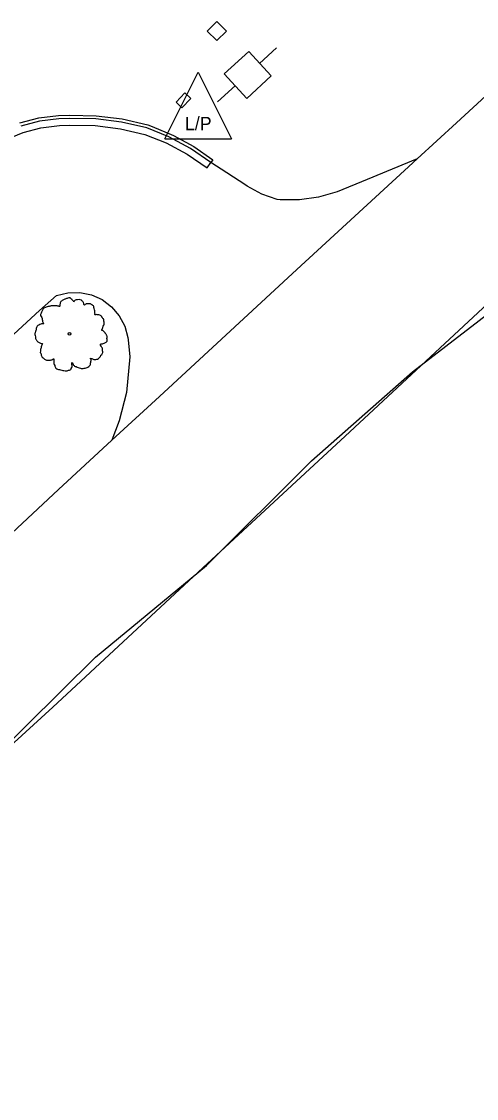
# Model space of a CAD drawing. Extents: x 2161152 to 2175754, y 602179 to 617749.
# Drawn here: x 2162836.6 to 2162905, y 605296.7 to 605458.4 of the extents above; entities that cross this region are included whole.
import ezdxf

# ---------------------------------------------------------------- set-up
doc = ezdxf.new("R2010")
doc.units = 0
for name, color, linetype in [('RD_EX_Conc_Curb', 7, 'Continuous'), ('RD_EX_Conc_Gutter', 7, 'Continuous'), ('RD_EX_Parking_Asphalt', 7, 'Continuous'), ('RD_EX_Road', 7, 'Continuous'), ('RD_EX_UT', 7, 'Continuous'), ('RD_EX_VEG', 7, 'Continuous')]:
    doc.layers.add(name, color=color, linetype=linetype)

msp = doc.modelspace()

# ---------------------------------------------------------------- linework, layer by layer
at = {"layer": 'RD_EX_Conc_Curb'}
msp.add_lwpolyline([(2162836.4, 605443.12), (2162839.27, 605443.88), (2162842.2, 605444.23), (2162843.89, 605444.31), (2162847.84, 605444.22), (2162851.76, 605443.73), (2162855.63, 605442.85), (2162856.29, 605442.61), (2162859.48, 605441.24), (2162862.52, 605439.57), (2162865.37, 605437.61), (2162865.17, 605437.32), (2162865.09, 605437.19), (2162862.04, 605439.28), (2162858.78, 605441.02), (2162855.48, 605442.37), (2162851.68, 605443.24), (2162847.8, 605443.72), (2162843.9, 605443.81), (2162842.25, 605443.73), (2162839.36, 605443.38), (2162836.56, 605442.65)], dxfattribs=at)
at = {"layer": 'RD_EX_Conc_Gutter'}
msp.add_lwpolyline([(2162834.32, 605440.64), (2162836.88, 605441.7), (2162839.55, 605442.4), (2162842.33, 605442.74), (2162843.91, 605442.81), (2162847.73, 605442.73), (2162851.5, 605442.26), (2162855.18, 605441.41), (2162858.36, 605440.12), (2162861.52, 605438.42), (2162864.53, 605436.37), (2162865.09, 605437.19)], dxfattribs=at)
at = {"layer": 'RD_EX_Parking_Asphalt'}
for points in [[(2162896.04, 605437.72), (2162888.57, 605434.62), (2162884.07, 605432.78), (2162881.27, 605431.99), (2162878.39, 605431.59), (2162875.48, 605431.58), (2162875.06, 605431.61), (2162872.72, 605432.44), (2162870.55, 605433.64), (2162870.32, 605433.79), (2162867.49, 605435.65), (2162865.09, 605437.19)], [(2162832.21, 605408.43), (2162839.36, 605414.97), (2162841.9, 605417.21), (2162843.62, 605417.64), (2162845.4, 605417.68), (2162847.14, 605417.33), (2162848.76, 605416.6), (2162850.18, 605415.54), (2162851.33, 605414.18), (2162852.15, 605412.61), (2162852.61, 605410.9), (2162852.66, 605410.57), (2162852.91, 605407.99), (2162852.41, 605402.64), (2162851.29, 605398.43), (2162850.22, 605395.49)]]:
    msp.add_lwpolyline(points, dxfattribs=at)
at = {"layer": 'RD_EX_Road'}
for points in [[(2162917.02, 605457), (2162901.98, 605443.14), (2162896.04, 605437.72), (2162894.14, 605435.98), (2162878, 605421.14), (2162857.37, 605402.08), (2162850.22, 605395.49), (2162842.2, 605388.11), (2162825.87, 605372.86), (2162813.54, 605361.31), (2162797.56, 605346.66), (2162791.94, 605341.38), (2162789, 605338.93), (2162786.7, 605336.94), (2162785.38, 605335.8), (2162769.2, 605321.32), (2162751.87, 605305.17), (2162746.09, 605299.88), (2162745.82, 605299.64), (2162744.83, 605298.73), (2162729.3, 605284.63)], [(2162610.98, 605142.74), (2162631.96, 605161.97), (2162654.13, 605182.45), (2162675.54, 605202.17), (2162697.6, 605222.63), (2162722.31, 605245.68), (2162738.68, 605260.91), (2162760.98, 605281.6), (2162781.23, 605300.15), (2162803.5, 605320.65), (2162820.96, 605336.83), (2162841.34, 605355.43), (2162863.86, 605376.35), (2162885.23, 605396.1), (2162904.45, 605413.96), (2162926, 605434.03)]]:
    msp.add_lwpolyline(points, dxfattribs=at)
at = {"layer": 'RD_EX_UT'}
for p, q in [((2162874.95, 605454.39), (2162872.39, 605452.05)), ((2162870.77, 605453.87), (2162867.08, 605450.5)), ((2162874.15, 605450.18), (2162870.77, 605453.87)), ((2162858.19, 605440.76), (2162863.19, 605450.76)), ((2162863.19, 605450.76), (2162868.19, 605440.76)), ((2162867.08, 605450.5), (2162870.46, 605446.81)), ((2162870.46, 605446.81), (2162874.15, 605450.18)), ((2162868.78, 605448.75), (2162866.09, 605446.29)), ((2162858.19, 605440.76), (2162868.19, 605440.76))]:
    msp.add_line(p, q, dxfattribs=at)
for points in [[(2162864.54, 605456.93), (2162866, 605455.48), (2162867.42, 605456.89), (2162865.96, 605458.35), (2162864.54, 605456.93)], [(2162859.85, 605446.25), (2162861.18, 605447.63), (2162862.06, 605446.79), (2162860.73, 605445.41), (2162859.85, 605446.25)]]:
    msp.add_lwpolyline(points, dxfattribs=at)
at = {"layer": 'RD_EX_VEG'}
msp.add_lwpolyline([(2162768.94, 605292.32), (2162782.97, 605302.54), (2162794.55, 605310.58), (2162805.73, 605319.37), (2162814.62, 605327.42), (2162832.11, 605347.44), (2162847.75, 605362.93), (2162864.42, 605376.7), (2162880.18, 605392.38), (2162895.34, 605405.76), (2162910.37, 605417.3)], dxfattribs=at)
for centre, radius in [((2162843.86, 605411.47), 0.188), ((2162843.85, 605411.46), 0.000075)]:
    msp.add_circle(centre, radius, dxfattribs=at)
for points in [[(2162843.95, 605416.85), (2162843.73, 605416.87), (2162843.49, 605416.79), (2162843.3, 605416.72), (2162843.13, 605416.66), (2162842.96, 605416.58), (2162842.74, 605416.45), (2162842.57, 605416.3), (2162842.47, 605416.12), (2162842.44, 605415.95), (2162842.4, 605415.74), (2162842.4, 605415.61), (2162842.3, 605415.59), (2162842.19, 605415.61), (2162842, 605415.67), (2162841.82, 605415.67), (2162841.63, 605415.67), (2162841.37, 605415.65), (2162841.11, 605415.65), (2162840.9, 605415.61), (2162840.66, 605415.57), (2162840.37, 605415.48), (2162840.11, 605415.38), (2162839.89, 605415.2), (2162839.7, 605414.84), (2162839.61, 605414.58), (2162839.49, 605414.39), (2162839.61, 605414.05), (2162839.74, 605413.79), (2162839.76, 605413.64), (2162839.81, 605413.32), (2162839.89, 605413.15), (2162839.98, 605413), (2162839.92, 605412.99), (2162839.64, 605412.95), (2162839.42, 605412.87), (2162839.1, 605412.7), (2162838.93, 605412.54), (2162838.86, 605412.29), (2162838.84, 605412.03), (2162838.76, 605411.88), (2162838.71, 605411.67), (2162838.69, 605411.62), (2162838.65, 605411.37), (2162838.73, 605411.04), (2162838.74, 605410.77), (2162838.84, 605410.61), (2162838.95, 605410.47), (2162839.08, 605410.29), (2162839.38, 605410.12), (2162839.62, 605410.04), (2162839.77, 605410.02), (2162839.64, 605409.65), (2162839.61, 605409.39), (2162839.51, 605409.09), (2162839.51, 605409.03), (2162839.47, 605408.68), (2162839.59, 605408.43), (2162839.64, 605408.15), (2162839.77, 605407.98), (2162839.98, 605407.76), (2162840.22, 605407.59), (2162840.6, 605407.49), (2162840.9, 605407.51), (2162841.33, 605407.64), (2162841.52, 605407.7), (2162841.5, 605407.57), (2162841.52, 605407.29), (2162841.52, 605406.97), (2162841.63, 605406.73), (2162841.71, 605406.52), (2162841.82, 605406.33), (2162842.06, 605406.16), (2162842.36, 605406.11), (2162842.68, 605406), (2162843.02, 605405.94), (2162843.39, 605405.92), (2162843.84, 605406.03), (2162844.05, 605406.13), (2162844.12, 605406.26), (2162844.27, 605406.54), (2162844.24, 605406.71), (2162844.25, 605407.16), (2162844.33, 605407.03), (2162844.46, 605406.76), (2162844.83, 605406.54), (2162845.13, 605406.41), (2162845.49, 605406.3), (2162845.72, 605406.24), (2162846.07, 605406.3), (2162846.35, 605406.35), (2162846.63, 605406.45), (2162846.86, 605406.65), (2162846.99, 605406.86), (2162847.03, 605407.06), (2162847.08, 605407.34), (2162847.12, 605407.48)], [(2162847.12, 605407.48), (2162847.07, 605407.61), (2162847.03, 605407.79), (2162847.08, 605407.78), (2162847.22, 605407.74), (2162847.42, 605407.64), (2162847.59, 605407.59), (2162847.83, 605407.61), (2162848.04, 605407.68), (2162848.38, 605407.89), (2162848.58, 605408.24), (2162848.79, 605408.54), (2162848.85, 605408.79), (2162848.81, 605408.96), (2162848.79, 605409.33), (2162848.64, 605409.52), (2162848.6, 605409.61), (2162848.53, 605409.91), (2162848.58, 605409.95), (2162848.79, 605409.99), (2162849.07, 605410.08), (2162849.28, 605410.17), (2162849.45, 605410.31), (2162849.5, 605410.47), (2162849.48, 605410.77), (2162849.52, 605411.07), (2162849.46, 605411.19), (2162849.39, 605411.3), (2162849.33, 605411.45), (2162849.22, 605411.56), (2162849.15, 605411.67), (2162849.07, 605411.75), (2162848.98, 605411.86), (2162848.85, 605411.96), (2162848.73, 605411.99), (2162848.7, 605412.11), (2162848.81, 605412.26), (2162848.85, 605412.33), (2162848.86, 605412.5), (2162849.03, 605412.76), (2162849.07, 605413.06), (2162849.03, 605413.38), (2162849, 605413.59), (2162848.88, 605413.79), (2162848.73, 605413.98), (2162848.64, 605414.11), (2162848.51, 605414.2), (2162848.26, 605414.3), (2162848.08, 605414.34), (2162847.81, 605414.34), (2162847.66, 605414.37), (2162847.68, 605414.41), (2162847.68, 605414.52), (2162847.68, 605414.73), (2162847.63, 605415.07), (2162847.51, 605415.44), (2162847.51, 605415.46), (2162847.44, 605415.65), (2162847.27, 605415.8), (2162847.14, 605415.87), (2162846.99, 605415.97), (2162846.8, 605415.98), (2162846.58, 605415.98), (2162846.37, 605415.95), (2162846.22, 605415.87), (2162846.09, 605415.78), (2162846.03, 605415.89), (2162845.96, 605416.12), (2162845.92, 605416.23), (2162845.81, 605416.36), (2162845.64, 605416.51), (2162845.3, 605416.6), (2162844.83, 605416.55), (2162844.61, 605416.4), (2162844.5, 605416.27), (2162844.46, 605416.36), (2162844.31, 605416.51), (2162844.24, 605416.64), (2162844.1, 605416.73), (2162843.99, 605416.81), (2162843.92, 605416.85)]]:
    msp.add_spline(points, degree=3, dxfattribs=at)

# ---------------------------------------------------------------- texts
at = {"layer": 'RD_EX_UT'}
msp.add_text('L/P', height=2, dxfattribs=at).set_placement((2162861.18, 605442.04))

doc.saveas('drawing.dxf')
